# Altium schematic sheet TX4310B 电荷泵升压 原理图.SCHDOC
size A; SheetNumber: 0; SheetTotal: 0
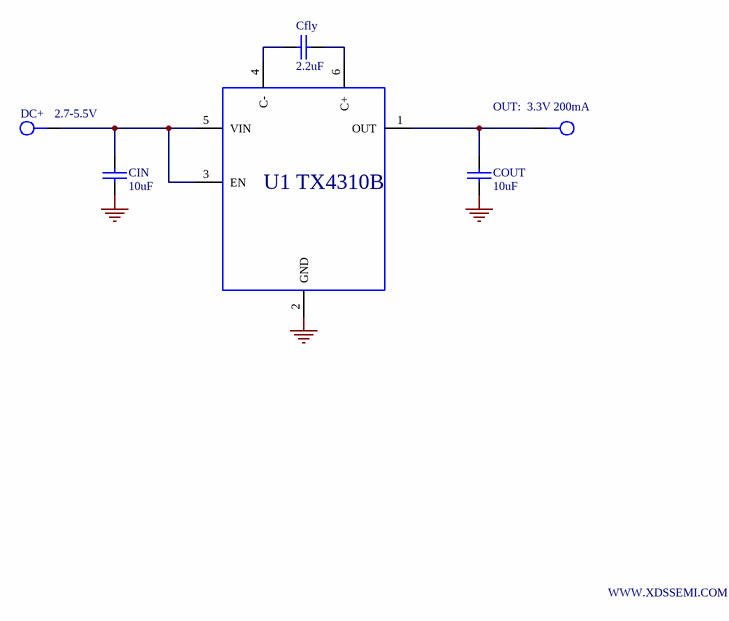
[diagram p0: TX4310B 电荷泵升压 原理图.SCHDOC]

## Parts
?  U1 TX4310B
Cfly  2.2uF  [C10*16]
CIN  10uF  [C10*16]
COUT  10uF  [C10*16]
DC+  2.7-5.5V  [P]
OUT:  3.3V 200mA  [P]

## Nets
GND: ?.2(GND) CIN.2 COUT.2
Net?_1: ?.1(OUT) COUT.1 OUT:.P
Net?_3: ?.3(EN) ?.5(VIN) CIN.1 DC+.P
Net?_4: ?.4(C-) Cfly.1
Net?_6: ?.6(C+) Cfly.2

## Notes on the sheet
- WWW.XDSSEMI.COM

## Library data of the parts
? = TX4310
Cfly CIN COUT = CAP: Capacitor
DC+ OUT: = P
